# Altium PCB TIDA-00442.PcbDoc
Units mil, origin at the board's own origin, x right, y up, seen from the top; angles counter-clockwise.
Board outline 2800 x 2450 mil, 4 copper layers (Top Layer, GND, POWER, Bottom Layer), stack 90 mil thick; 95 components, 40 nets, 194 pads, 43 vias.
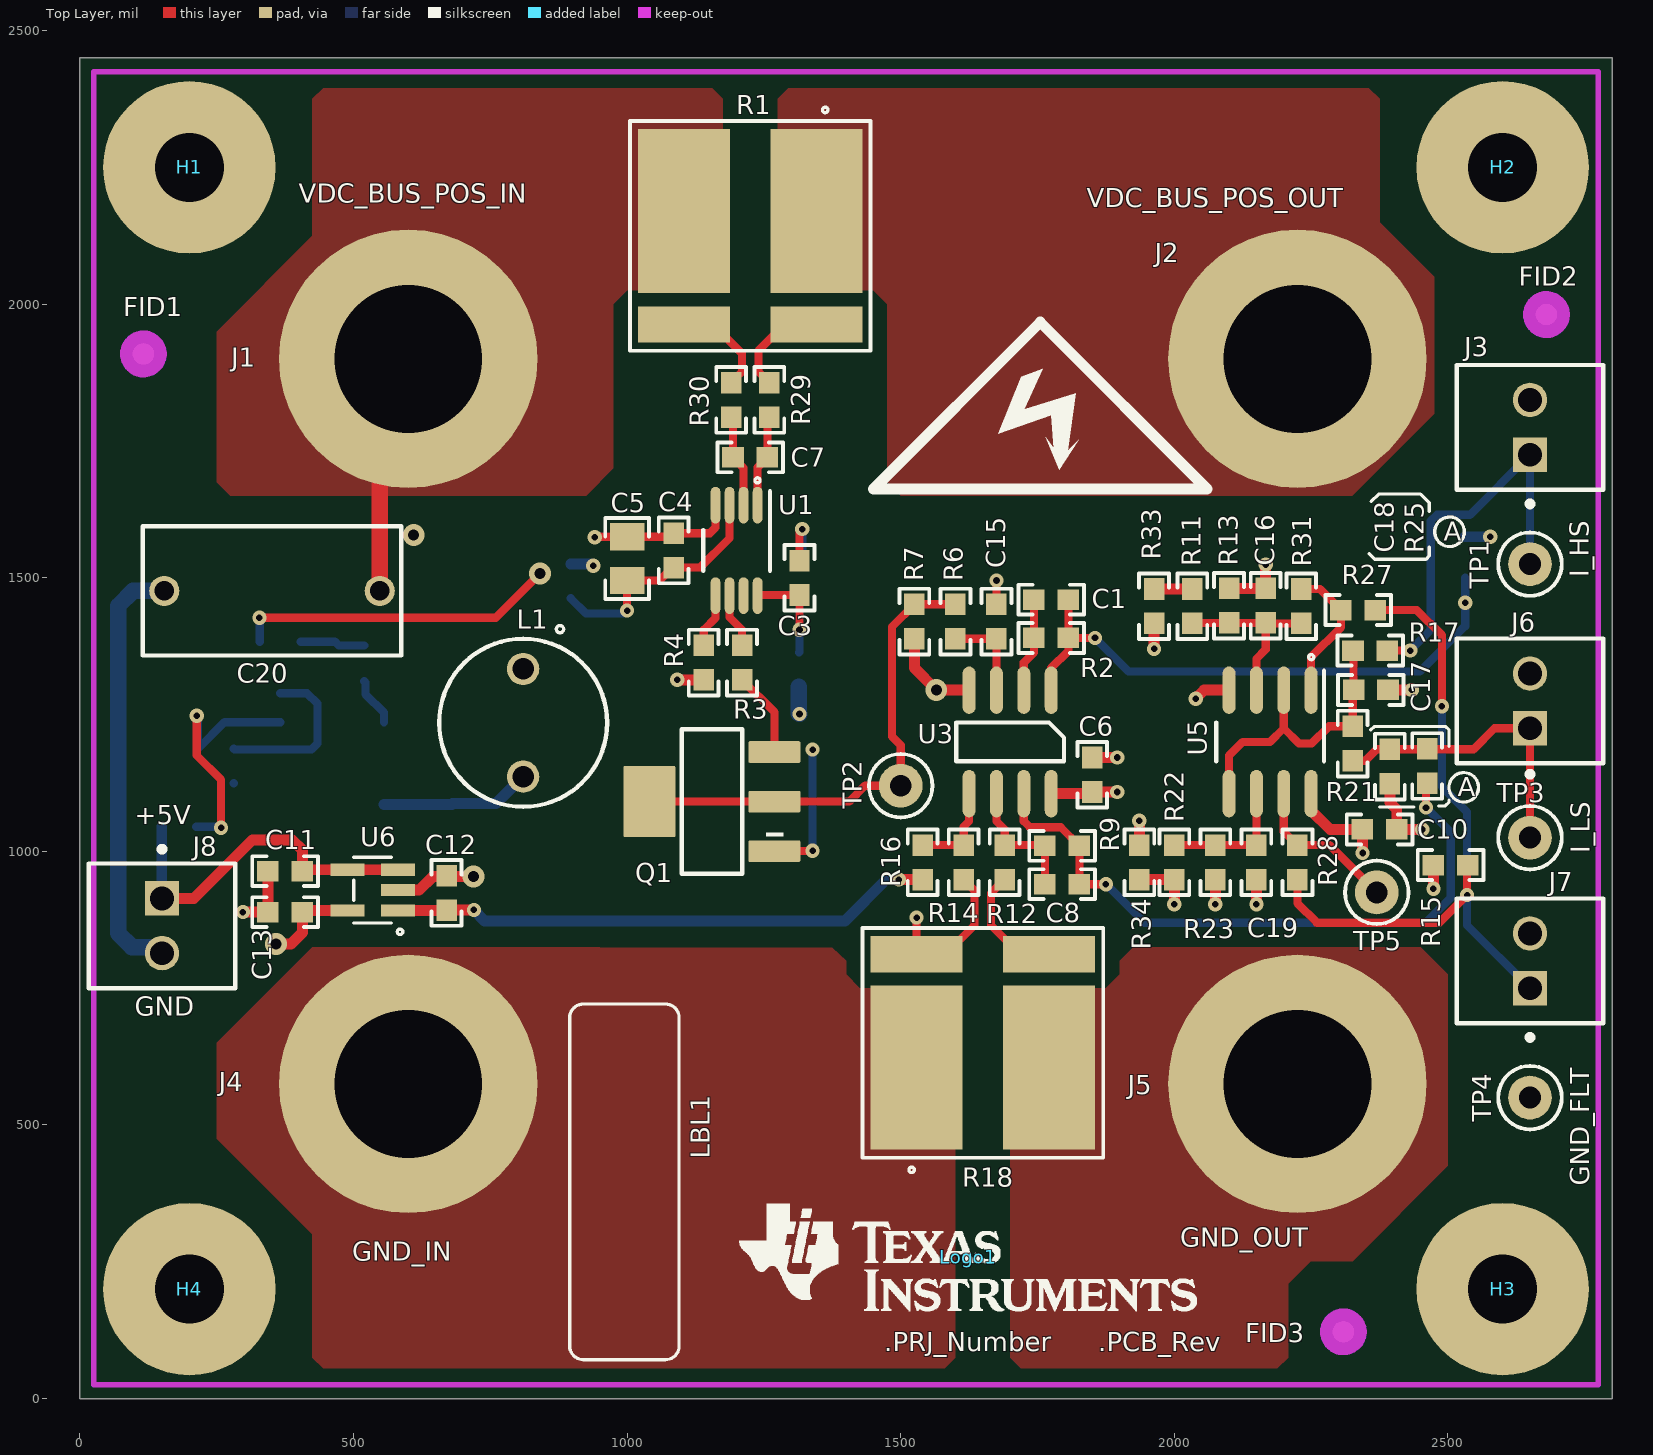
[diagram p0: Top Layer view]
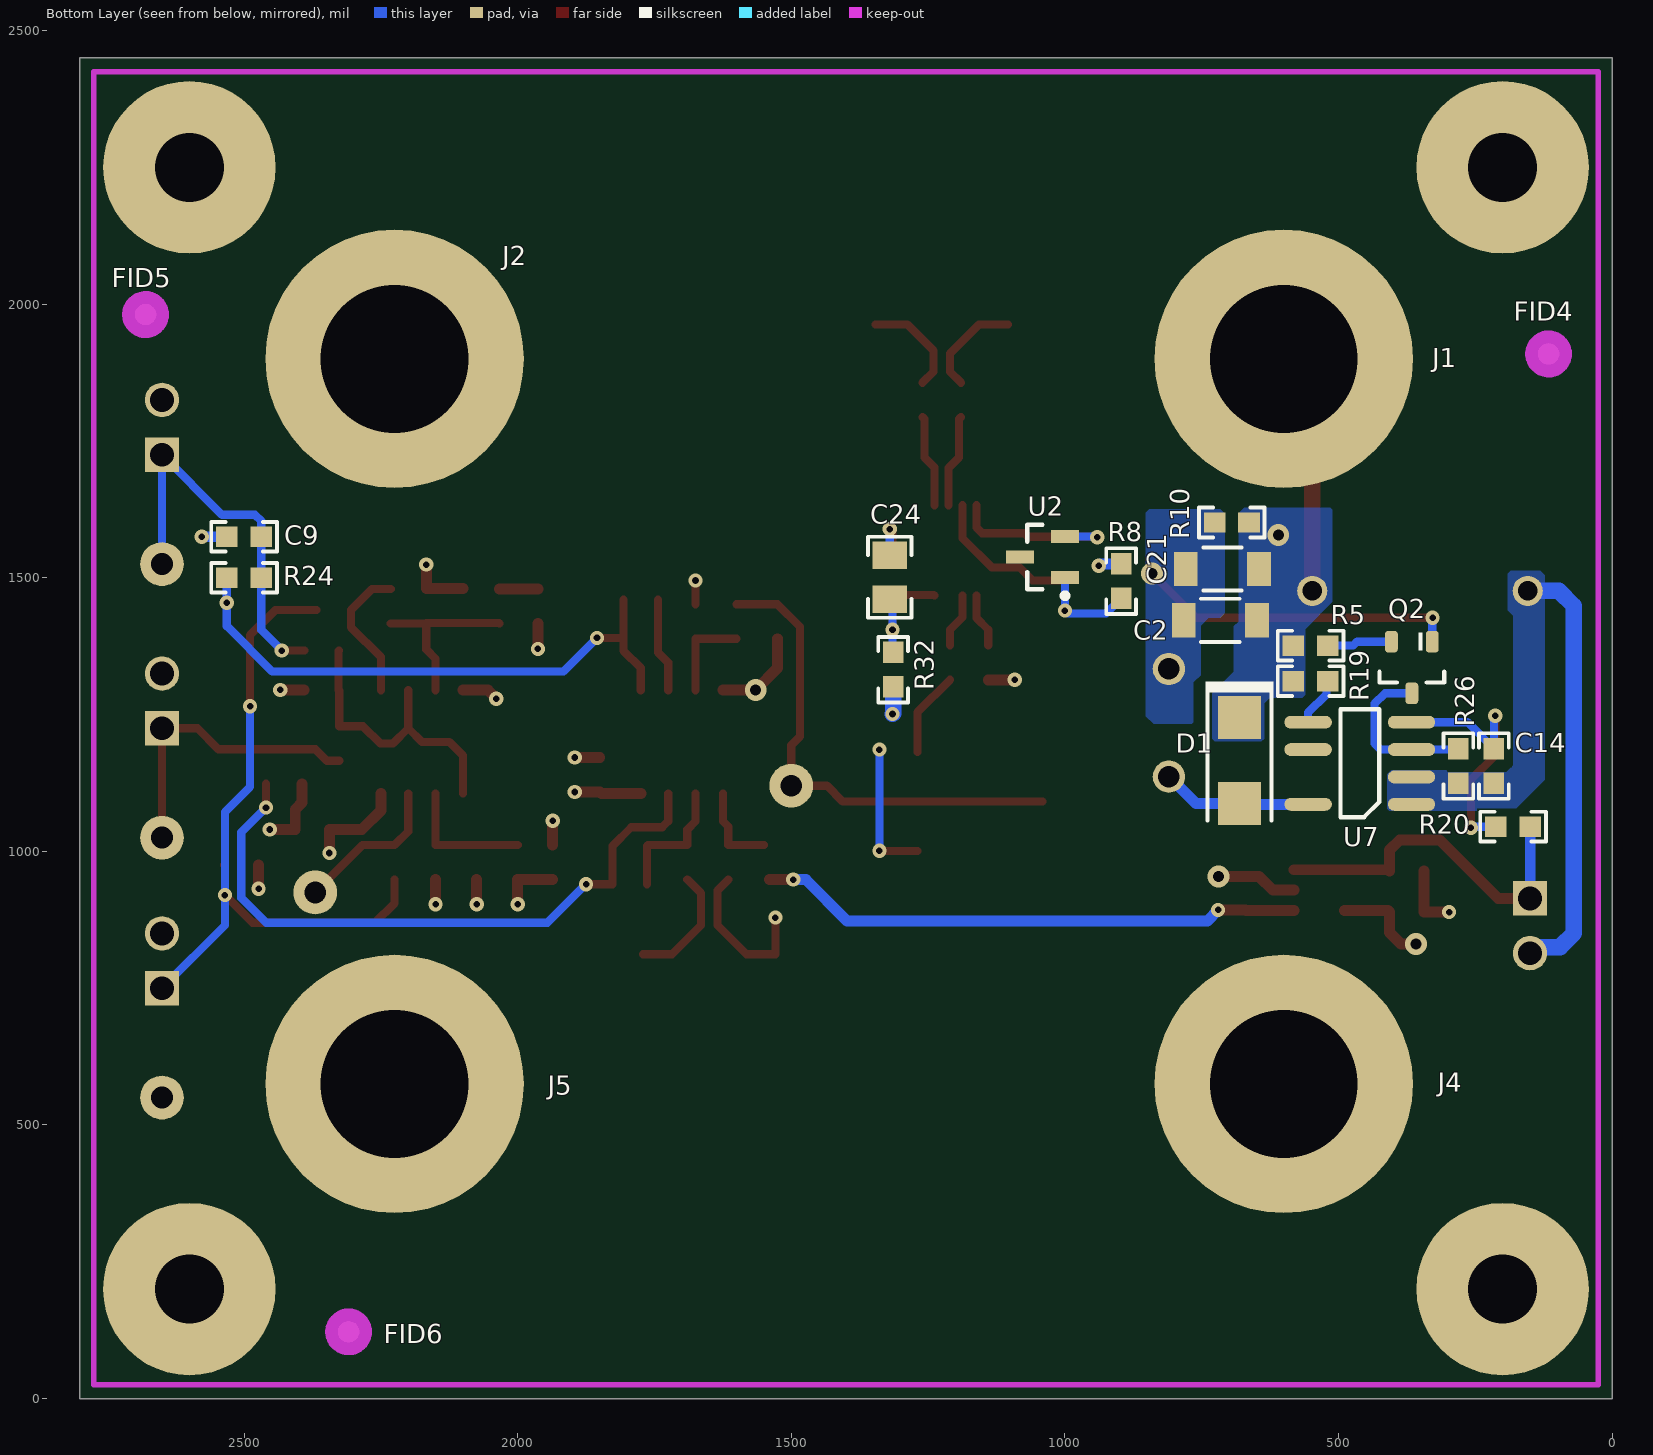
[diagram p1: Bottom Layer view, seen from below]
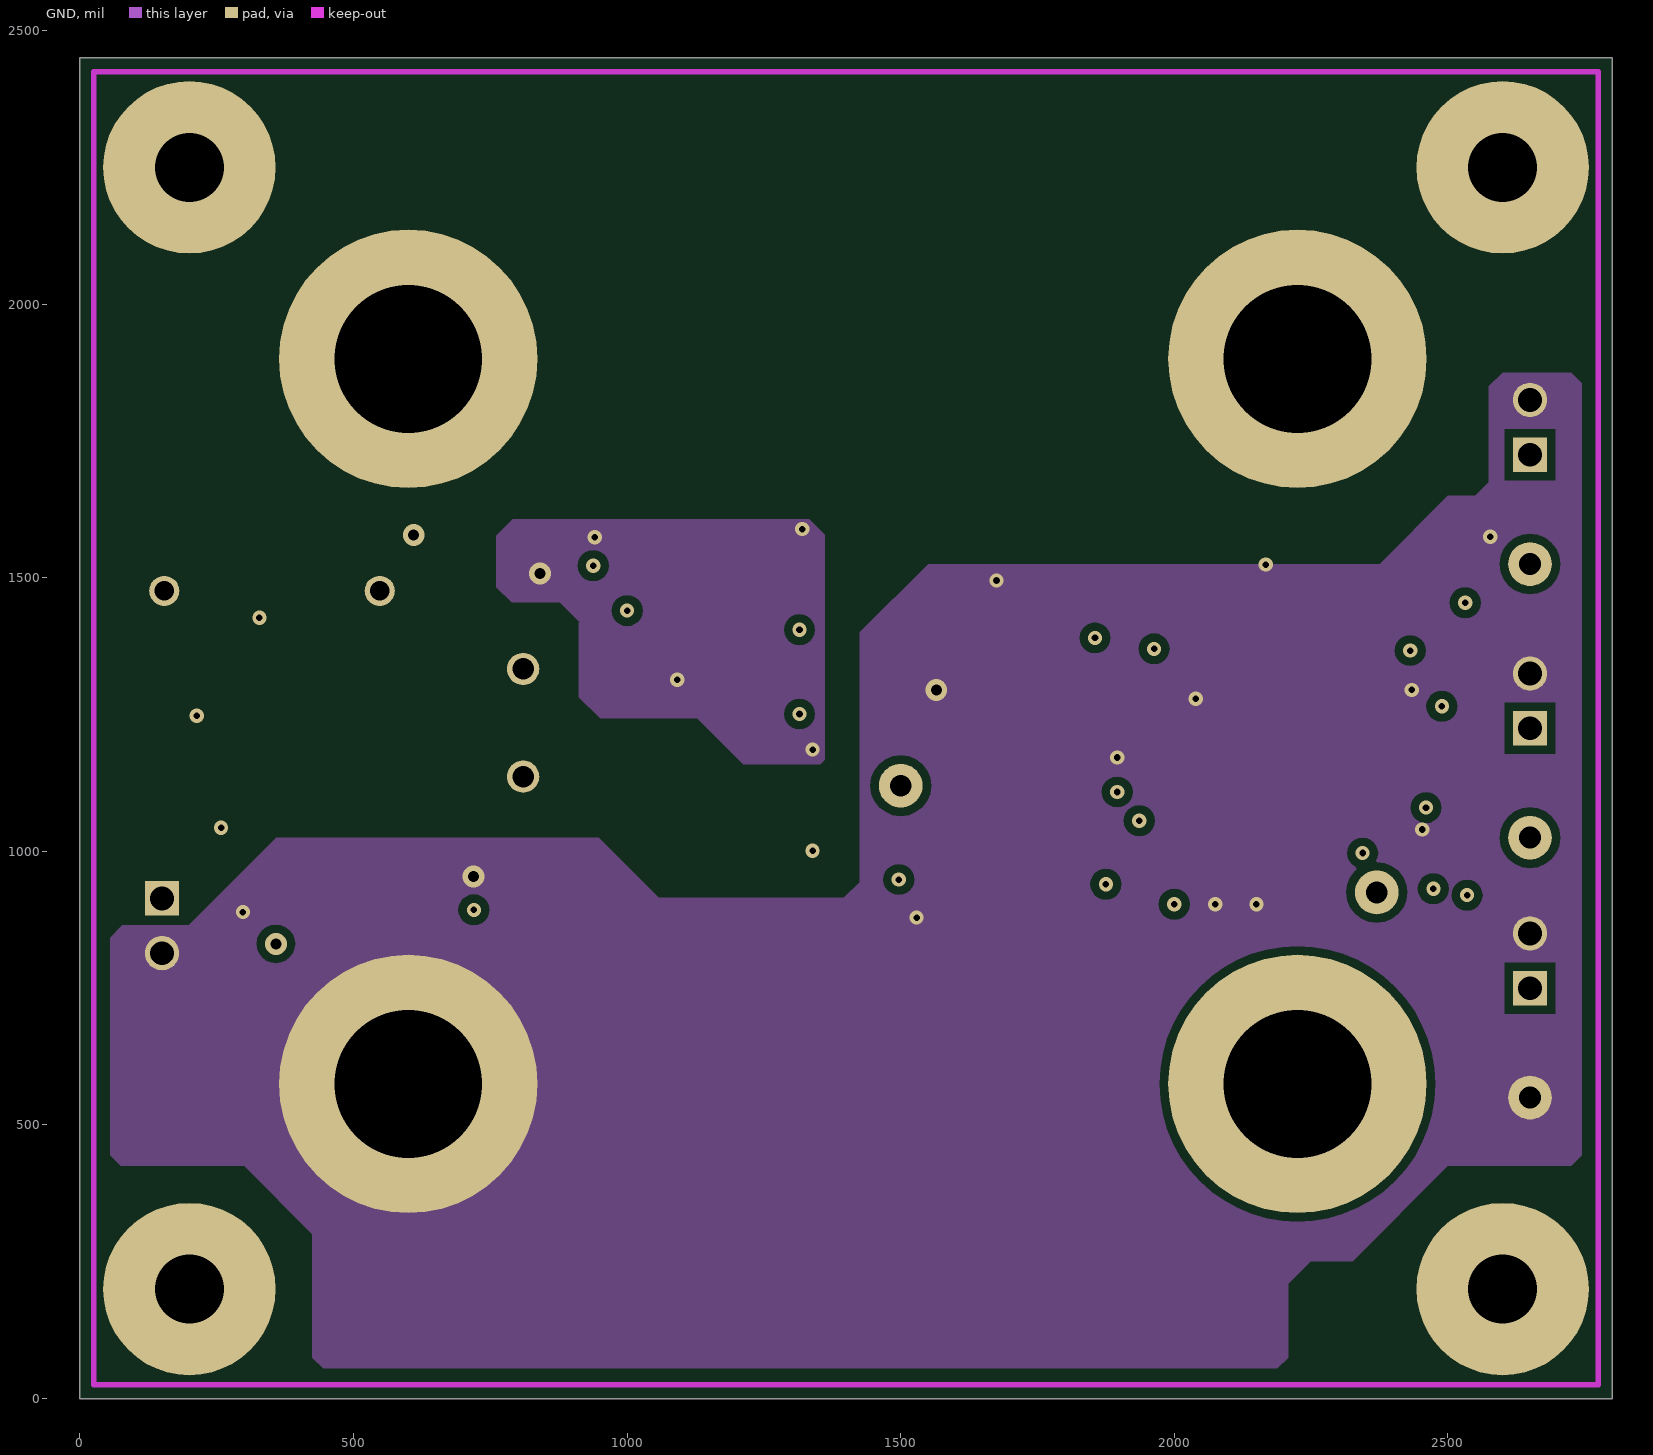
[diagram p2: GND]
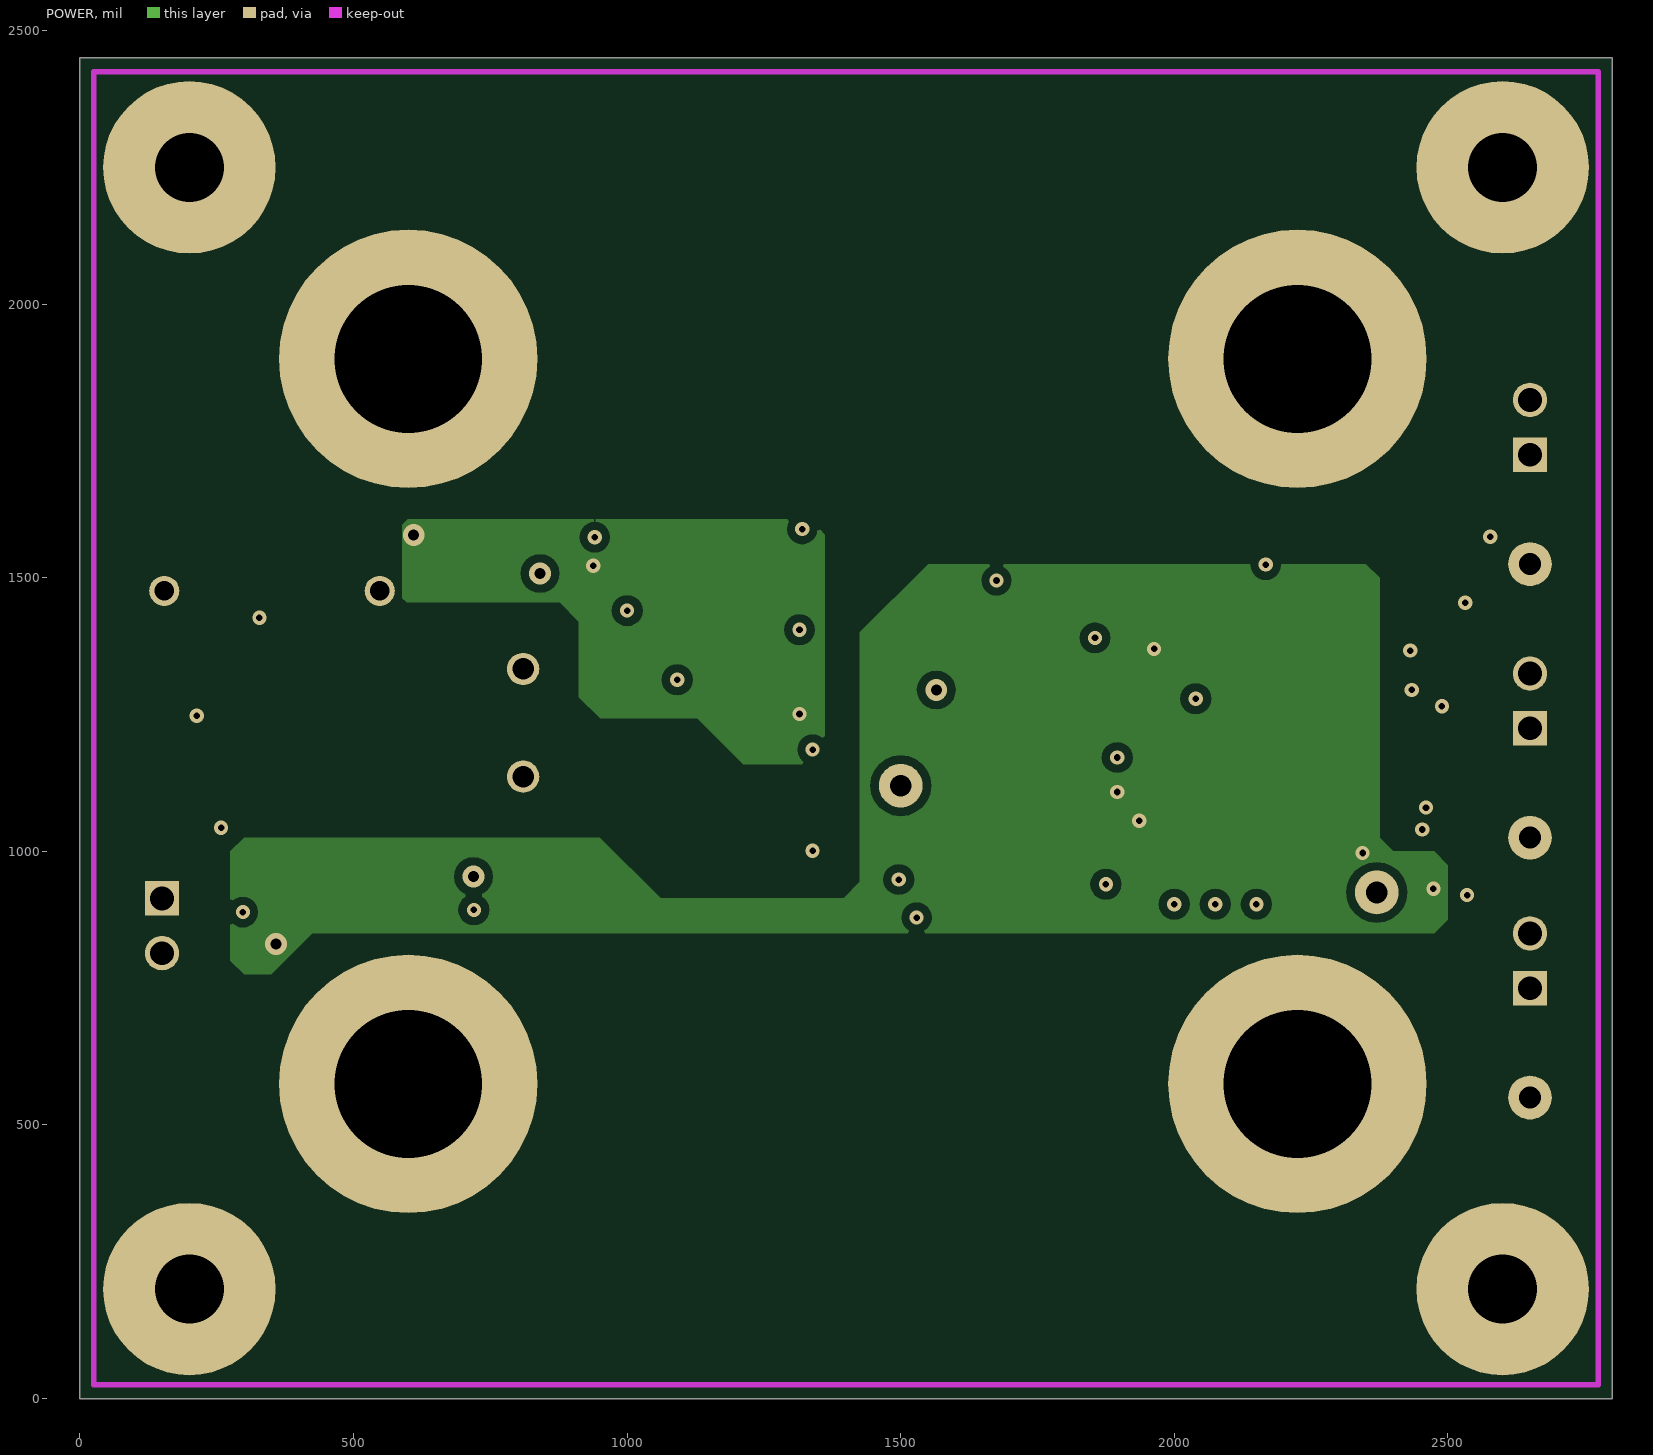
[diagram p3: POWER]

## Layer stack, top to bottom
Top Layer: signal copper 1.4
Dielectric: core 59.2, FR-4, Dk 4.8
GND: signal copper 1.4
Dielectric: prepreg 12.6, FR-4, Dk 4.8
POWER: signal copper 1.4
Dielectric: core 12.6, FR-4, Dk 4.8
Bottom Layer: signal copper 1.4

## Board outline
0,0 0,2450 2800,2450 2800,0

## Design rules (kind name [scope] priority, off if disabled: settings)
AcuteAngle [All] p1: minimum=4.50000000000000E+0001 checktracksonly=FALSE
AssemblyTestPointUsage [All] p1: valid=2
Clearance Poly_Poly [InPolygon vs InPolygon] p1: gap=25
Clearance Clearance_BoardEdge_MountingHoles [OnCopper and InComponentClass('Mounting Holes') vs IsKeepOut] p2: gap=12
Clearance Clearance_BoardEdge_Poly [OnCopper and InPoly vs IsKeepOut] p3: gap=25
Clearance Clearance_BoardEdge [OnCopper and Not InComponentClass('Logo') and not InComponentClass('FiducialMark') and not InRegion(1000,500,4000,800) and Not IsKeepout vs IsKeepOut] p4: gap=25
Clearance Clearance_Poly [InPolygon] p5: gap=15
Clearance [All] p6: gap=7.87
ComponentClearance ComponentClearance_MountingHoles_FiducialMarks [InComponentClass('Mounting Holes') vs InComponentClass('FiducialMark')] p1: gap=50 collisioncheckmode=3 verticalgap=10 showdistances=FALSE
ComponentClearance ComponentClearance_Shunt [InComponentClass('Header') vs InComponentClass('Shunt')] p2: gap=0 collisioncheckmode=3 verticalgap=0 showdistances=FALSE
ComponentClearance ComponentClearance_Logo [InComponentClass('Logo')] p3: gap=50 collisioncheckmode=3 verticalgap=10 showdistances=FALSE
ComponentClearance ComponentClearance_ScrewToNut [(HasFootprint('NY PMS 440 0025 PH')) vs (HasFootprint('Keystone_1902C'))] p4: gap=5 collisioncheckmode=3 verticalgap=10 showdistances=FALSE
ComponentClearance ComponentClearance_MountingHoles [InComponentClass('Mounting Holes')] p5: gap=100 collisioncheckmode=3 verticalgap=0 showdistances=FALSE
ComponentClearance ComponentClearance_SmallPassives [HasFootprint('0201*') or HasFootprint('0402*') or HasFootprint('0508') or HasFootprint('0603*') or HasFootprint('0612') or HasFootprint('0805*') or HasFootprint('0815*') or HasFootprint('0830*') or HasFootprint('1206*') or HasFootprint('1210*') or HasFootprint('1808*') or HasFootprint('1812*') or HasFootprint('1825*') or HasFootprint('2010*') or HasFootprint('2220*') or HasFootprint('2225*') or HasFootprint('2512*') or HasFootprint('2728*') or HasFootprint('3518*') vs HasFootprint('0201*') or HasFootprint('0402*') or HasFootprint('0508') or HasFootprint('0603*') or HasFootprint('0612') or HasFootprint('0805*') or HasFootprint('0815*') or HasFootprint('0830*') or HasFootprint('1206*') or HasFootprint('1210*') or HasFootprint('1808*') or HasFootprint('1812*') or HasFootprint('1825*') or HasFootprint('2010*') or HasFootprint('2220*') or HasFootprint('2225*') or HasFootprint('2512*') or HasFootprint('2728*') or HasFootprint('3518*')] p6: gap=10 collisioncheckmode=3 verticalgap=10 showdistances=FALSE
ComponentClearance ComponentClearance_THtoSMT [IsThruComponent vs IsSMTComponent] p7: gap=40 collisioncheckmode=3 verticalgap=30 showdistances=FALSE
ComponentClearance ComponentClearance_THtoTH [IsThruComponent vs IsThruComponent] p8: gap=65 collisioncheckmode=3 verticalgap=30 showdistances=FALSE
ComponentClearance [All] p9: gap=30 collisioncheckmode=3 verticalgap=10 showdistances=FALSE
DiffPairsRouting [All] p1: maxlimit=100 minlimit=10 mostfreqgap=10 maxuncoupledlength=1000
FabricationTestPointUsage TestPointUsage [All] p1: valid=2 allowmultiple=FALSE
FabricationTestpoint Testpoint [All] p1: side=3 testpointundercomponent=TRUE minsize=40 maxsize=100 preferedsize=60 minholesize=0 maxholesize=40 preferedholesize=32 testpointgrid=1 allowsidetop=TRUE allowsidebottom=TRUE usegrid=TRUE gridtolerance=0.01
FanoutControl Fanout_LCC [IsLCC] p1: bgadir=Out bgaviamode=Centered fanoutstyle=Auto fanoutdirection=Alternating viagrid=1 // Fanout_LCC (Default Rule)
FanoutControl Fanout_BGA [IsBGA] p2: bgadir=Out bgaviamode=Centered fanoutstyle=Auto fanoutdirection=Alternating viagrid=1 // Fanout_BGA (Default Rule)
FanoutControl Fanout_Default [All] p4: bgadir=Out bgaviamode=Centered fanoutstyle=Auto fanoutdirection=Alternating viagrid=1 // Fanout_Default (Default Rule)
FanoutControl Fanout_Small [(CompPinCount < 5)] p5: bgadir=Out bgaviamode=Centered fanoutstyle=Auto fanoutdirection=OutThenIn viagrid=1 // Fanout_Small (Default Rule)
HoleSize [All] p1: absolutevalues=TRUE maxlimit=270 minlimit=8 maxpercent=80.000 minpercent=20.000
MinimumAnnularRing MinimumAnnularRing_ThermalPadVias [IsVia and InAnyComponent] p1: minimumring=5.91
MinimumAnnularRing [All] p2: minimumring=7
MinimumSolderMaskSliver MinimumSolderMaskSliver_Logo [InComponentClass('Logo') vs InComponentClass('Logo')] p1: minsoldermaskwidth=0.7
MinimumSolderMaskSliver [All] p2: minsoldermaskwidth=3.94
PlaneConnect [All] p1: planeconnectstyle=Direct reliefexpansion=10 reliefentries=4 reliefconductorwidth=10 reliefairgap=10
PolygonConnect [All] p1: connectstyle=Direct reliefconductorwidth=10 reliefentries=4 polygonreliefangle="90 Angle"
RoutingVias ThermalPadVias [IsVia and InAnyComponent] p1: holewidth=7.87 width=19.68 viastyle="Through Hole" minholewidth=7.87 minwidth=19.68 maxholewidth=12.99 maxwidth=23.62
RoutingVias [All] p2: holewidth=12 width=26 viastyle="Through Hole" minholewidth=7.87 minwidth=26 maxholewidth=20 maxwidth=40
SilkToSilkClearance SilkToSilkClearance_Pb-FreeLogo [(HasFootprint('Pb-Free_Overlay_Medium') OR HasFootprint('Pb-Free_Overlay_Small')) vs (HasFootprint('Pb-Free_Overlay_Medium') OR HasFootprint('Pb-Free_Overlay_Small'))] p1: silktosilkclearance=0
SilkToSilkClearance [All] p2: silktosilkclearance=5
SilkscreenOverComponentPads "Silk to Solder Mask Opening" [IsPad] p1: minsilkscreentomaskgap=1
SolderMaskExpansion [All] p1: expansion=2.5
Width [All] p1: maxlimit=100 minlimit=6 preferedwidth=10 checkconnectedcopper=TRUE
14 further rules are at their usual default settings.

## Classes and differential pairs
component class Label: LBL1
component class Sh02_Current_sense: C1 C2 C3 C4 C5 C6 C7 C8 C9 C10 C11 C12 C13 C14 C15 C16 C17 C18 C19 C20 C21 C24 D1 J1 J2 J3 J4 J5 J6 J7 J8 L1 Q1 Q2 R1 R2 R3 R4 R5 R6 R7 R8 R9 R10 R11 R12 R13 R14 R15 R16 R17 R18 R19 R20 R21 R22 R23 R24 R25 R26 R27 R28 R29 R30 R31 R32 R33 R34 TP1 TP2 TP3 TP4 TP5 U1 U2 U3 U5 U6 U7
component class AssemblyNote: ZZ1 ZZ2 ZZ3 ZZ4
component class FiducialMark: FID1 FID2 FID3 FID4 FID5 FID6
component class Sh03_TID_Hardware: FID1 FID2 FID3 FID4 FID5 FID6 H1 H2 H3 H4 LBL1 Logo1 ZZ1 ZZ2 ZZ3 ZZ4
component class Logo: Logo1
component class "Mounting Holes": H1 H2 H3 H4

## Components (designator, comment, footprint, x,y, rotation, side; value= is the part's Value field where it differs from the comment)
C1 "GRM1885C1H101JA01D" 0603 1775,1460 r180 top
C2 "CL31A106KBHNNNE" 1206_190 716,1422 r0 bottom
C3 "GRM188R71H104KA93D" 0603 1315,1500 r90 top
C4 "GRM188R71H104KA93D" 0603 1085,1550 r90 top
C5 "GRM21BR71H105KA12L" 0805_HV 1000,1535 r90 top
C6 "GRM188R71H104KA93D" 0603 1850,1140 r270 top
C7 "0603ZC103KAT2A" 0603 1225,1720 r180 top
C8 "GRM1885C1H101JA01D" 0603 1795,940 r180 top
C9 "GRM188R71H104KA93D" 0603 2500,1575 r0 bottom
C10 "GRM188R71H104KA93D" 0603 2375,1040 r180 top
C11 "GRM188R71H104KA93D" 0603 375,964 r180 top
C12 "GRM188R71H104KA93D" 0603 670,924 r90 top
C13 "GRM188R71H104KA93D" 0603 375,889 r180 top
C14 "GRM188R71H104KA93D" 0603 216,1156 r270 bottom
C15 "GRM1885C1H101JA01D" 0603 1675,1420 r90 top
C16 "GRM188R71H821KA01D" 0603 2167,1449 r270 top
C17 "GRM188R71H821KA01D" 0603 2359,1295 r180 top
C18 "GRM188R71H104KA93D" 0603 2394,1155 r270 top
C19 "GRM188R71H821KA01D" 0603 2150,980 r90 top
C20 "ECQ-E6333KF" ECQE_1200x1290x600 351,1476 r180 top
C21 "CL31A106KBHNNNE" 1206_190 712,1516 r0 bottom
C24 "08055C105KAT2A" 0805_HV 1320,1501 r90 bottom
D1 "STTH1R06A" SMA 681,1166 r270 bottom
FID1 "Fiducial" Fiducial10-20 116,1909 r0 top
FID2 "Fiducial" Fiducial10-20 2680,1981 r0 top
FID3 "Fiducial" Fiducial10-20 2309,122 r0 top
FID4 "Fiducial" Fiducial10-20 116,1909 r90 bottom
FID5 "Fiducial" Fiducial10-20 2680,1981 r90 bottom
FID6 "Fiducial" Fiducial10-20 2309,122 r90 bottom
H1 "NY PMS 440 0025 PH" "NY PMS 440 0025 PH" 200,2250 r0 top locked
H2 "NY PMS 440 0025 PH" "NY PMS 440 0025 PH" 2600,2250 r0 top locked
H3 "NY PMS 440 0025 PH" "NY PMS 440 0025 PH" 2600,200 r0 top locked
H4 "NY PMS 440 0025 PH" "NY PMS 440 0025 PH" 200,200 r0 top locked
J1 "3267" Pomona_3267 600,1900 r180 bottom
J2 "3267" Pomona_3267 2225,1900 r180 bottom
J3 "282834-2" TEC_282834-2 2650,1775 r90 top
J4 "3267" Pomona_3267 600,575 r0 bottom
J5 "3267" Pomona_3267 2225,575 r90 bottom
J6 "282834-2" TEC_282834-2 2650,1275 r90 top
J7 "282834-2" TEC_282834-2 2650,800 r90 top
J8 "282834-2" TEC_282834-2 150,864 r270 top
L1 "680 µH" 8095 810,1235 r270 top
LBL1 "Size: 0.65\" x 0.20 \"" Label_650x200 995,396 r90 top
Logo1 "Texas Instruments" TI_Stacked_Overlay_Small 1623.04,258.07 r0 top
Q1 "ZVP0545GTA" SOT-223 1155,1091 r180 top
Q2 "PBHV9050T,215" SOT-23 366,1336 r270 bottom
R1 "WSL36375L000FEA" WSL3637_0.001 1225,2125 r180 top
R2 "RC0603FR-0716KL" 0603 1775,1390 r0 top
R3 "CRCW06034K99FKEA" 0603 1210,1345 r90 top
R4 "RT0603BRD0724K3L" 0603 1140,1345 r90 top
R5 "CRCW06031M47FKEA" 0603 551,1376 r0 bottom
R6 "RC0603JR-070RL" 0603 1600,1420 r270 top
R7 "RG1608P-163-B-T5" 0603 1525,1420 r90 top
R8 "CRCW0603200KFKEA" 0603 897,1494 r90 bottom
R9 "RG1608P-163-B-T5" 0603 1795,1010 r0 top
R10 "CRCW0603402KFKEA" 0603 695,1601 r180 bottom
R11 "RC0603FR-0716KL" 0603 2033,1448 r270 top
R12 "RG1608P-102-B-T5" 0603 1690,980 r270 top
R13 "CRCW060316K2FKEA" 0603 2100,1449 r90 top
R14 "RG1608P-102-B-T5" 0603 1615,980 r90 top
R15 "CRCW060315K0FKEA" 0603 2505,975 r0 top
R16 "RG1608P-163-B-T5" 0603 1540,980 r270 top
R17 "CRCW060316K2FKEA" 0603 2358,1367 r180 top
R18 "WSL36375L000FEA" WSL3637_0.001 1650,650 r0 top
R19 "RC0603JR-070RL" 0603 551,1311 r180 bottom
R20 "RC0603JR-070RL" 0603 181,1045 r180 bottom
R21 "CRCW060316K2FKEA" 0603 2326,1197 r270 top
R22 "CRCW060316K2FKEA" 0603 2000,980 r90 top
R23 "RC0603FR-0716KL" 0603 2075,980 r270 top
R24 "CRCW060338R3FKEA" 0603 2500,1500 r180 bottom
R25 "CRCW060338R3FKEA" 0603 2462,1156 r90 top
R26 "CRCW060351K0JNEA" 0603 281,1156 r90 bottom
R27 "RC0603JR-070RL" 0603 2336,1441 r0 top
R28 "RC0603JR-070RL" 0603 2225,980 r270 top
R29 "CRCW060322R0JNEA" 0603 1260,1825 r270 top
R30 "CRCW060322R0JNEA" 0603 1190,1825 r270 top
R31 "CRCW06035M11FKEA" 0603 2232,1448 r90 top
R32 "RG1608P-103-B-T5" 0603 1314,1332 r270 bottom
R33 "RC0603JR-070RL" 0603 1963,1448 r90 top
R34 "RC0603JR-070RL" 0603 1936,980 r270 top
TP1 "5000" Keystone5000 2650,1525 r90 top
TP2 "5000" Keystone5000 1500,1120 r90 top
TP3 "5000" Keystone5000 2650,1025 r90 top
TP4 "5001" Keystone5001 2650,550 r270 top
TP5 "5000" Keystone5000 2370,925 r0 top
U1 "INA170EA/2K5" DGK0008A_N 1200,1550 r270 top
U2 "LM4040DIM3X-2.5" MF03A_N 1041,1538 r0 bottom
U3 "OPA2376AID" D0008A_N 1700,1200 r270 top
U5 "TLC372CDR" D0008A_N 2175,1200 r270 top
U6 "REF2033AIDDCR" DDC0005A_N 535,929 r180 top
U7 "UCC28880DR" D0007A_N 461,1161 r0 bottom
ZZ1 "This Assembly Note is for PCB labels only" AssemblyNoteLabel 181,3474 r0 top
ZZ2 "These assemblies are ESD sensitive, ESD precautions shall be observed." AssemblyNote 181,3379 r0 top
ZZ3 "These assemblies must be clean and free from flux and all contaminants. Use of no clean flux is not acceptable." AssemblyNote 181,3289.56 r0 top
ZZ4 "These assemblies must comply with workmanship standards IPC-A-610 Class 2, unless otherwise specified." AssemblyNote 181,3201 r0 top

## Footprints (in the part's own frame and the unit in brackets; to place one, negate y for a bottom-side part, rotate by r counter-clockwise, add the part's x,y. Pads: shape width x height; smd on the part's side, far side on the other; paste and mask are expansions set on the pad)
0603 [mm] "0603 from SM-752 data"
  rect 1x0.95 smd: 1(-0.8,0) 2(0.8,0)
  silkscreen extent -1.52,-0.69 1.52,0.69, body extent -0.87,-0.47 0.87,0.47, height 0.85
0805_HV [mil] "0805 with 30mil clearance between pads"
  rect 50x63 smd: 1(-40,0) 2(40,0)
  silkscreen extent -74,-40 74,40, body extent -43,-29 43,29, height 43
1206_190 [mm] "1206_190"
  rect 1.1x1.6 smd: 1(-1.7,0) 2(1.7,0)
  silkscreen extent -0.9,-1 0.9,1, body extent -1.75,-0.95 1.75,0.95, height 1.9
8095 [mm] "THT, 2-PIN, Body (7.8 X7.8 mm),pitch 5mm"
  round 1.5 hole 1 paste+0: 1(-2.5,0) 2(2.5,0)
  silkscreen extent -3.9,-3.9 3.9,3.9, body extent -5.52,-5.52 5.52,5.52, height 9.5
AssemblyNote [mil] "Assembly Note"
AssemblyNoteLabel [mil] "Assembly Note for PCB Labels"
D0007A_N [mm] "SOIC, 7-Leads, Body 4.9x3.9mm, Pitch 1.27mm, IPC Medium Density"
  oval 2.2x0.6 smd: 1(-2.4,1.905) 2(-2.4,0.635) 3(-2.4,-0.635) 4(-2.4,-1.905) 5(2.4,-1.905) 6(2.4,-0.635) 8(2.4,1.905)
  silkscreen extent -0.9,-2.5 0.9,2.5, body extent -3,-2.5 3,2.5, height 1.54
D0008A_N [mm] "SOIC, 8-Leads, Body 4.9x3.9mm, Pitch 1.27mm, IPC Medium Density"
  oval 2.2x0.6 smd: 1(-2.4,1.905) 2(-2.4,0.635) 3(-2.4,-0.635) 4(-2.4,-1.905) 5(2.4,-1.905) 6(2.4,-0.635) 7(2.4,0.635) 8(2.4,1.905)
  silkscreen extent -0.9,-2.5 0.9,2.5, body extent -3,-2.45 3,2.45, height 1.63
DDC0005A_N [mil]
  rect 62x22 smd: 1(-46,37.4) 2(-46,0) 3(-46,-37.4) 4(46,-37.4) 5(46,37.4)
  silkscreen extent -55,-60 35,81, body extent -60,-60 60,60, height 43
DGK0008A_N [mm] "TSOP, 8-Leads, Body 3x3mm, Pitch 0.65mm, IPC Medium Density"
  oval 1.7x0.45 smd mask+0.05: 1(-2.1,0.975) 2(-2.1,0.325) 3(-2.1,-0.325) 4(-2.1,-0.975) 5(2.1,-0.975) 6(2.1,-0.325) 7(2.1,0.325) 8(2.1,0.975)
  silkscreen extent -2.75,-1.55 0.95,1.55, body extent -2.45,-1.5 2.45,1.5, height 0.94
ECQE_1200x1290x600 [mm] "TH, 2-Leads, Body 12x6mm, Pin Spacing 10mm"
  round 1.4 hole 0.9: 1(-5,0) 2(5,0)
  silkscreen extent -6,-3 6,3, body extent -6,-3 6,3, height 12.9
Fiducial10-20 [mm]
  round 1 smd mask+0.5: 1(0,0)
  Top Layer keep-out circle w1.178: c0,0 r0.5
Keystone5000 [mil] "For Keystone 500x miniature loop terminals"
  round 80 hole 40: 1(0,0)
  silkscreen extent -58,-58 58,58, body extent -49,-49 49,49, height 182
Keystone5001 [mil] "For Keystone 500x miniature loop terminals"
  round 80 hole 40: 1(0,0)
  silkscreen extent -58,-58 58,58, body extent -49,-49 49,49, height 182
Label_650x200 [mil] "Thermal Transfer Label"
  round 1 on Mech13: 0(0,0)
  silkscreen extent -325,-100 325,100, body extent -326,-101 326,101, height 1
MF03A_N [mm] "SOT23, 3-Leads, Body 2.9x1.3mm, Pitch 0.95mm, Lead Span 2.4mm, IPC Medium Density"
  rect 1.3x0.6 smd: 1(-1.05,0.95) 2(-1.05,-0.95) 3(1.05,0)
  silkscreen extent -1.17,-1.5 0.7,1.92, body extent -0.7,-1.5 0.7,1.5, height 1.12
"NY PMS 440 0025 PH" [mm] "4-40 nylon screw and mounting hole"
  round 8 hole 3.2: 1(0,0)
  body extent -3.3,-3.3 3.3,3.3, height 2.69
Pomona_3267 [mm] "Standard Uninsulated Banana Jack"
  round 12 hole 6.858: 1(0,0)
  body extent -4.13,-4.82 4.26,4.85, height 2.79
SMA [mm] "Molded Diode, 2-Leads, Body 4.3x2.6mm, IPC Medium Density, based on OnSemi component dimensions and land pattern"
  rect 2x2 smd: 1(-2,0) 2(2,0)
  silkscreen extent -3.66,-1.57 2.79,1.57, body extent -2.6,-1.3 2.6,1.3, height 2.42
SOT-23 [mm] "SOT23, 3-Leads, Body 2.9x1.3mm, Pitch 0.95mm, Lead Span 2.5mm, IPC Medium Density"
  rrect50% 1x0.6 smd: 1(-1.2,0.95) 2(-1.2,-0.95) 3(1.2,0)
  silkscreen extent -1.63,-1.5 0.7,1.5, body extent -1.16,-1.45 1.21,1.45, height 1
SOT-223 [mm] "SOT223/SC73, 4-Leads, Body 6.5x3.5mm, Pitch 2.3mm, Lead Span 7mm, IPC Medium Density"
  rrect10% 2.4x1 smd: 1(-2.9,2.3) 2(-2.9,0) 3(-2.9,-2.3)
  rrect4% 2.4x3.3 smd: 4(2.9,0)
  silkscreen extent -3.33,-3.35 1.4,3.35, body extent -3.5,-3.25 3.5,3.25, height 1.62
TEC_282834-2 [mm] "TEC"
  rect 1.6x1.6 hole 1.1: 1(-1.27,0)
  round 1.6 hole 1.1: 2(1.27,0)
  silkscreen extent -3.66,-3.4 2.9,3.4, body extent -2.77,-3.25 2.77,3.25, height 10.01
TI_Stacked_Overlay_Small [mil]
  silkscreen extent -418,-98 418,98
WSL3637_0.001 [mil] "Vishay WSL3637 recommended land pattern for 0.001 to 0.0019 Ohm"
  rect 168x300 smd: 1(-121,-45) 2(121,-45)
  rect 168x66 smd: 3(-121,162) 4(121,162)
  silkscreen extent -220,-210 220,210, body extent -185,-190 185,190, height 35

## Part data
C1 C8 C15: "CAP, CERM, 100 pF, 50 V, +/- 5%, C0G/NP0, 0603"
C2 C21: "CAP, CERM, 10 µF, 50 V, +/- 10%, X5R, 1206_190"
C3 C4 C6 C9 C10 C11 C12 C13 C14 C18: "CAP, CERM, 0.1 µF, 50 V, +/- 10%, X7R, 0603"
C5 C24: "CAP, CERM, 1 µF, 50 V, +/- 10%, X7R, 0805"
C7: "CAP, CERM, 0.01 µF, 10 V, +/- 10%, X7R, 0603"
C16 C17 C19: "CAP, CERM, 820 pF, 50 V, +/- 10%, X7R, 0603"
C20: "CAP, Film, 0.033 µF, 630 V, +/- 10%, TH"
D1: "Diode, Ultrafast, 600 V, 1 A, SMA"
FID1 FID2 FID3 FID4 FID5 FID6: "Fiducial mark.  There is nothing to buy or mount."
H1 H2 H3 H4: "Machine Screw, Round, #4-40 x 1/4, Nylon, Philips panhead"
J1 J2 J4 J5: "Standard Banana Jack, Uninsulated"
J3 J6 J7 J8: "Terminal Block, 2x1, 2.54mm, TH"
L1: library part "WE-TI HV 8095, 768772681", "SMD-Radial Leaded Wire Wound  Inductor WE-TI HV, L=680 µH"
LBL1: library part THT-14-423-10, "Thermal Transfer Printable Labels, 0.650\" W x 0.200\" H - 10,000 per roll"
Logo1: library part TI_Logo, "Texas Instrument Corporate Signature"
Q1: library part ZXMP6A17GTA, "MOSFET, P-CH, -450 V, 75 mA, SOT-223"
Q2: library part "PBHV9050T,215, NXP Semiconductor", "Transistor, PNP, 500 V, 0.15 A, SOT-23"
R1 R18: library part WSL36371L000FEA, "RES, 0.005, 1%, 3 W, WSL3637"
R2 R11 R23: "RES, 16.0 k, 1%, 0.1 W, 0603"
R3: "RES, 4.99 k, 1%, 0.1 W, 0603"
R4: "RES, 24.3 k, 0.1%, 0.1 W, 0603"
R5: "RES, 1.47 M, 1%, 0.1 W, 0603"
R6 R19 R20 R27 R28 R33 R34: "RES, 0, 5%, 0.1 W, 0603"
R7 R9 R16: "RES, 16.0 k, 0.1%, 0.1 W, 0603"
R8: "RES, 200 k, 1%, 0.1 W, 0603"
R10: "RES, 402 k, 1%, 0.1 W, 0603"
R12 R14: "RES, 1.00 k, 0.1%, 0.1 W, 0603"
R13 R17 R21 R22: "RES, 16.2 k, 1%, 0.1 W, 0603"
R15: "RES, 15.0 k, 1%, 0.1 W, 0603"
R24 R25: "RES, 38.3, 1%, 0.1 W, 0603"
R26: "RES, 51 k, 5%, 0.1 W, 0603"
R29 R30: "RES, 22, 5%, 0.1 W, 0603"
R31: "RES, 5.11 M, 1%, 0.1 W, 0603"
R32: "RES, 10.0 k, 0.1%, 0.1 W, 0603"
TP1 TP2 TP3 TP5: "Test Point, Miniature, Red, TH"
TP4: "Test Point, Miniature, Black, TH"
U1: "High-Side, Bidirectional Current Shunt Monitor, DGK0008A"
U2: "Precision Micropower Shunt Voltage Reference, 3-pin SOT-23"
U3: "Precision, Low Noise, Low Quiescent Current Operational Amplifier, 2 to 5.5 V, -40 to 125 degC, 8-pin SOIC (D0008A), Green (RoHS & no Sb/Br)"
U5: "LinCMOS Dual Differential Comparators, D0008A"
U6: "Low-Drift, Low-Power, Dual-Output, VREF and VREF / 2 Voltage References, DDC0005A"
U7: "700-V Lowest Quiescent Current Off-Line Switcher, D0007A"
ZZ1: library part AssemblyNoteLabel
ZZ2 ZZ3 ZZ4: library part AssemblyNote

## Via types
v1: diameter 26, hole 12, Top Layer to Bottom Layer, tented both sides, 38 vias
v2: diameter 40, hole 20, Top Layer to Bottom Layer, tented both sides, 5 vias

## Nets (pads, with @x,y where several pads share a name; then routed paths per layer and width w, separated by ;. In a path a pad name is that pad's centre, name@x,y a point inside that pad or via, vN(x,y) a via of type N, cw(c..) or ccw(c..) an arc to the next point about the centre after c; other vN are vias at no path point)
DC_BUS_POS: C2.1 C20.1 C21.1 D1.1 J1.1 R1.2 R5.2 R8.2 R10.2 R19.1 R32.2 | length 546
  Top Layer w30: C20.1@547.85,1468 C20.1 547.85,1847.85 J1.1
  Bottom Layer w20: R8.2 934.5,1525.5 v1(938,1522)
  Bottom Layer w30: R32.2 1314,1252 v1(1315,1251)
  other v2: 610,1578
FB: Q2.3 R26.2 U7.3 | length 306.9
  Bottom Layer w15: R26.2 282.5,1186 U7.3 423,1186 434,1197 434,1270 415.24,1288.76 Q2.3
FLOAT_REF: C2.2 C3.2 C4.2 C5.2 C21.2 C24.2 L1.1 Q1.1 Q2.1 R4.1 R10.1 U1.4 U2.2 | length 1330.5
  Top Layer w10: C4.2@1068.5,1575 C4.2@1075,1581.5 ; v1@1338.45,1000.45 v1(1339,1001)
  Top Layer w15: v1(328,1427) 760,1427 v2(841,1508) ; v1(941,1574) 942,1575 C5.2 C4.2@1068.5,1575 ; C4.2@1075,1581.5 1151.5,1581.5 1161.61,1591.61 U1.4 ; Q1.1 v1@1338.45,1000.45 ; C3.2 1315,1584 v1(1320,1589)
  Top Layer w20: v1(1091.5,1313.5) R4.1
  Bottom Layer w15: v1(328,1427) v1@328.6,1427.6 ; Q2.1 v1@328.6,1427 ; v1(941,1574) 942.4,1575.4 U2.2 ; C24.2 v1(1320,1589) ; v1(1339,1001) v1(1339,1186)
GND: C6.1 C9.2 C10.1 C11.2 C12.2 C13.2 C14.2 C15.2 C16.1 C17.1 C18.2 C19.1 C20.2 J3.2 J4.1 J6.2 J7.2 J8.2 R7.1 R13.2 R14.1 R18.1 R18.3 R23.2 R26.1 TP4.1 U3.4 U5.4 U6.2 U7.1 U7.2 | length 2102.1
  Top Layer w10: v1@1673.5,1495 v1@1673.5,1501.5
  Top Layer w15: v1(1529,879) R18.3 1582,812 1635,865 1635,928.5 R14.1 ; v1@1673.5,1495 1675,1493.5 C15.2
  Top Layer w20: v1(297.83,889) C13.2 C11.2 ; U6.2 620,929 645,954 v2(719,954) ; R7.1 1525,1335 v2(1565,1295) 1565.51,1294.49 U3.4 ; C6.1 v1(1895.67,1171.5) ; v1(2039,1279) 2054.49,1294.49 U5.4 ; v1(2075,903.5) R23.2 ; R13.2 C16.1 v1(2167,1524) ; v1(2150,903.5) C19.1 ; C17.1 v1(2434,1295) ; C18.2 2394,1089 2406.5,1076.5 C10.1 v1(2452.99,1040) v1@2455,1042.01
  Bottom Layer w20: C9.2 v1(2577.17,1575)
  Bottom Layer w30: J8.2@150,825 95,825 70,850 70,1449 97,1476 C20.2
  other v1: 1675,1495
GND_FAULT: J7.1 R15.2 R27.2 R28.2 | length 1296.9
  Top Layer w15: R28.2 2225,905 2260.37,869.63 2484.63,869.63 v1(2535,920) 2535,973.5 R15.2 ; R27.2 2443,1441 2489,1395 v1(2489,1265)
  Bottom Layer w15: v1(2489,1265) 2489,1118 2535,1072 v1(2535,920) 2535,865 J7.1
I_HS: C9.1 J3.1 R17.1 R24.2 TP1.1 | length 725.4
  Top Layer w15: R17.1 v1(2431,1367)
  Bottom Layer w15: v1(2431,1367) 2468.5,1404.5 R24.2 C9.1 2468.5,1603.5 2480,1615 2540,1615 J3.1 TP1.1
I_LS: C18.1 J6.1 R21.2 R25.2 TP3.1 | length 548.6
  Top Layer w15: R21.2 2348.5,1165.5 2369.5,1186.5 C18.1 2460,1186.5 2546.5,1186.5 2585,1225 J6.1 TP3.1
NetC1_1: C1.1 R2.2 R24.1 U3.1 | length 1051.8
  Top Layer w15: U3.1 1775,1335 1806.5,1366.5 R2.2 ; C1.1 R2.2 ; v1(1855,1390) R2.2
  Bottom Layer w15: v1(1855,1390) 1916.37,1328.63 2448.63,1328.63 2531.5,1411.5 v1(2531.5,1454.33) R24.1
NetC1_2: C1.2 R2.1 U3.2 | length 173.2
  Top Layer w15: U3.2 1725,1345 1743.5,1363.5 R2.1 C1.2
NetC3_1: C3.1 C24.1 R32.1 U1.8 | length 240.6
  Top Layer w15: U1.8 1239.57,1468.5 C3.1 v1(1315,1405)
  Bottom Layer w15: R32.1 1315,1364.5 1315,1417 1315,1456 C24.1
NetC7_1: C7.1 R29.2 U1.1 | length 169.8
  Top Layer w15: U1.1 1238.39,1701.89 C7.1 1256.5,1790 R29.2
NetC7_2: C7.2 R30.2 U1.2 | length 170.3
  Top Layer w15: R30.2 1193.5,1790 C7.2 1212.8,1700.71 U1.2
NetC8_1: C8.1 R9.2 R25.1 U3.7 | length 1194.2
  Top Layer w15: U3.7 1725,1055 1735.93,1044.07 1792.42,1044.07 R9.2 C8.1 v1(1875,940) ; v1(2460,1080) R25.1@2460,1123.5
  Bottom Layer w15: v1(1875,940) 1945.37,869.63 2459.63,869.63 2505,915 2505,1035 v1(2460,1080)
NetC8_2: C8.2 R9.1 R12.1 U3.6 | length 244.4
  Top Layer w15: U3.6 1675,1055 1690,1040 R12.1 1762.01,1011.5 R9.1 C8.2
NetC14_1: C14.1 R20.1 U7.4 | length 504
  Top Layer w15: v1(213.5,1248) 213.5,1175.5 258,1131 v1(258,1043)
  Bottom Layer w15: R20.1 256,1045 v1(258,1043) ; v1(213.5,1248) 212,1248 216,1244 C14.1 264.5,1236 U7.4
NetC15_1: C15.1 R6.2 U3.3 | length 169
  Top Layer w15: R6.2 C15.1 U3.3
NetC16_2: C16.2 R11.2 R13.1 R31.1 U5.3 | length 329.9
  Top Layer w15: R11.2 2034,1417.5 R13.1 C16.2 ; U5.3 2150,1352 2167,1369 C16.2 ; R31.1 2168,1416.5 C16.2
NetC17_2: C17.2 R17.2 R21.1 U5.2 U5.5 | length 549.9
  Top Layer w15: U5.5 2100,1175 2125,1200 2175,1200 2200,1225 ; U5.2 2200,1225 ; R17.2 2327.5,1366 C17.2 2326,1293.5 R21.1 2282.5,1228.5 2251,1197 2228,1197 2200,1225
NetC19_2: C19.2 R22.2 R23.1 U5.6 | length 244
  Top Layer w15: R22.2 R23.1 C19.2 U5.6
NetD1_2: D1.2 L1.2 U7.8 | length 275.5
  Bottom Layer w20: U7.8 679.74,1086 D1.2 760.68,1087.26 L1.2
NetJ2_1: J2.1 R1.1
NetJ5_1: J5.1 R18.2
NetQ1_2: Q1.2 Q1.4 R6.1 R7.2 TP2.1 | length 901.3
  Top Layer w15: Q1.4 Q1.2 1406,1091 1435,1120 TP2.1 1500,1194 1484,1210 1484,1410.5 R7.2 R6.1
NetQ1_3: Q1.3 R3.1 | length 156.5
  Top Layer w15: R3.1 1269.17,1254.33 Q1.3
NetQ2_2: Q2.2 R5.1 | length 119.1
  Bottom Layer w15: Q2.2 465.76,1383.24 473,1376 R5.1
NetR1_3: R1.3 R29.1 | length 192.7
  Top Layer w15: R29.1 1240,1876.5 1240,1915 1288,1963 R1.3
NetR1_4: R1.4 R30.1 | length 189.7
  Top Layer w15: R1.4 1157,1963 1210,1910 1210,1876.5 R30.1
NetR3_2: R3.2 U1.6 | length 100.3
  Top Layer w15: U1.6 1187.2,1427.8 1210,1405 R3.2
NetR4_2: R4.2 U1.5 | length 99.8
  Top Layer w15: R4.2 1140,1405 1161.61,1426.61 U1.5
NetR11_1: R11.1 R33.2 | length 70
  Top Layer w20: R33.2 R11.1
NetR12_2: R12.2 R18.4 | length 221.8
  Top Layer w15: R12.2 1665,923.5 1665,865 1718,812 R18.4
NetR14_2: R14.2 R16.1 U3.5 | length 163.2
  Top Layer w15: R16.1@1550,1011.5 R14.2 1615,1045 1625,1055 U3.5
NetR19_2: R19.2 U7.5 | length 89.9
  Bottom Layer w15: R19.2 522,1308.5 522,1287 555.49,1253.51 U7.5
NetR22_1: R22.1 R34.2 | length 109
  Top Layer w20: R34.2 R22.1 v1(2000,903.5)
NetR27_1: R27.1 R31.2 U5.1 | length 257.5
  Top Layer w15: R31.2 2266.01,1479.5 R27.1 2304.5,1409.5 2250,1355 U5.1
NetR28_1: R28.1 TP5.1 U5.7 | length 285.2
  Top Layer w15: U5.7 2200,1036.5 R28.1 2283.5,1011.5 TP5.1
P3P3V: C6.2 C10.2 C13.1 R15.1 R33.1 R34.1 U3.8 U5.8 U6.5 | length 614.1
  Top Layer w20: v2(358,831) 386,831 406.5,851.5 C13.1 409.09,891.6 U6.5 ; U3.8 C6.2@1847.01,1105.51 ; C6.2 v1(1895.67,1108.5) ; R34.1 v1(1936,1056) ; v1(1963,1370) R33.1 ; U5.8 2250,1075 2285,1040 C10.2 2343.5,997.5 v1(2344,997) ; R15.1 v1(2473.5,931.5) v1@2475,930
P5V: C11.1 J8.1 R20.2 U6.3 U6.4 | length 653.7
  Top Layer w20: J8.1 208,914 315,1021 388,1021 406.5,1002.5 C11.1 408.9,966.4 U6.4 U6.3
  Bottom Layer w20: R20.2 149.5,914.5 J8.1
VREF_1P65V: C12.1 R16.2 U6.1 | length 999.2
  Top Layer w20: U6.1 669.09,891.6 C12.1 v1@720.5,892.5 ; v1(1496.5,948.5) R16.2
  Bottom Layer w20: v1@720,892.5 739.5,873 1398,873 1473.5,948.5 v1(1496.5,948.5)
  other v1: 720,893
VREF_2P5V: C4.1 C5.1 R8.1 U1.3 U2.1 | length 512.3
  Top Layer w15: v1(1000,1440) C5.1 1059,1495 1082.5,1518.5 1133.5,1518.5 1187.2,1572.2 U1.3
  Bottom Layer w15: R8.1 925,1434.5 994.5,1434.5 v1(1000,1440) 999.66,1440.34 U2.1
pads on no net: FID1.1 FID2.1 FID3.1 FID4.1 FID5.1 FID6.1 H1.1 H2.1 H3.1 H4.1 LBL1.0 U1.7 U2.3 U7.6

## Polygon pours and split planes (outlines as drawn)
NetJ5_1 on Top Layer "Multi-Layer-No Net" (solid, remove dead copper, pour order 18): 1725,50 1700,75 1700,725 1725,750 1875,750 1900,775 1900,800 1925,825 2450,825 2500,775 2500,425 2326,251 2249,251 2208,210 2208,75 2183,50
DC_BUS_POS on Top Layer "Multi-Layer-No Net" (solid, remove dead copper, pour order 12): 250,1950 425,2125 425,2375 450,2400 1150,2400 1175,2375 1175,2050 1150,2025 1000,2025 975,2000 975,1700 925,1650 275,1650 250,1675
NetJ2_1 on Top Layer "Multi-Layer-No Net" (solid, remove dead copper, pour order 15): 1275,2375 1275,2050 1300,2025 1450,2025 1475,2000 1475,1675 1500,1650 2325,1650 2475,1800 2475,2050 2375,2150 2375,2375 2350,2400 1300,2400
GND on Top Layer "Multi-Layer-No Net" (solid, remove dead copper, pour order 17): 250,650 425,825 950,825 1375,824.2 1400,800 1400,775 1425,750 1575,750 1600,725 1600,75 1575,50 450,50 425,75 425,300 250,475
DC_BUS_POS on POWER "Multi-Layer-No Net" (solid, remove dead copper, pour order 22): 589,1597 589,1463 597,1455 877,1455 912,1420 912,1282 951,1243 1128,1243 1212,1159 1353,1159 1361,1167 1361,1579 1333,1607 599,1607
P3P3V on POWER "Multi-Layer-No Net" (solid, remove dead copper, pour order 20): 950,1025 1061,914 1395.43,914 1425,944.21 1425,1400 1550,1525 2350,1525 2375,1500 2375,1025 2400,1000 2475,1000 2500,975 2500,875 2475,850 425,850 350,775 300,775 275,800 275,1000 300,1025
GND on GND "Multi-Layer-No Net" (solid, remove dead copper, pour order 14): 50,837 77.24,865 199,865 359,1025 948.2,1024.54 1058,915 1396,915 1425,944 1425,1400 1550,1525 2375,1525 2500,1650 2550,1650 2575,1675 2575,1850 2600,1875 2725,1875 2750,1850 2750,450 2725,425 2500,425 2326,251 2249,251 2208,210 2208,75 2188,55 444.74,55.26 425,75 425,300 300,425 75,425 50,450
FLOAT_REF on GND "Multi-Layer-No Net" (solid, remove dead copper, pour order 21): 761,1577 761,1483 789,1455 877,1455 913,1419 912,1418 912,1282 951,1243 1128,1243 1212,1159 1353,1159 1361,1167 1361,1579 1333,1607 791,1607
GND on Bottom Layer "Multi-Layer-No Net" (solid, remove dead copper, pour order 16): 123,1505 123,1131 180,1074 407,1074 411,1078 411,1141 404,1148 303,1148 300,1145 193,1145 181,1157 181,1431 191,1441 191,1507 185,1513 131,1513
DC_BUS_POS on Bottom Layer "Multi-Layer-No Net" (solid, remove dead copper, pour order 13): 515,1628 511,1624 511,1456 561,1406 561,1286 566,1281 626,1281 636,1271 636,1206 641,1201 726,1201 731,1206 731,1288.67 691,1328.67 691,1411 682,1420 682,1618 672,1628
FLOAT_REF on Bottom Layer "Multi-Layer-No Net" (solid, remove dead copper, pour order 19): 768,1233 838,1233 852,1247 852,1619 846,1625 716,1625 708,1617 708,1435 716,1427 737,1427 752,1412 752,1322 765,1309 765,1236

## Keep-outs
Keep-Out Layer:
  lines w10: 25,25 25,2425 2775,2425 2775,25 25,25
  text ".Layer_Name" at 577,-858.49 h60

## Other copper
Top Layer:
  text ".Layer_Name" at 577,-858.49 h60
GND:
  text ".Layer_Name" at 701,-865.49 h60
POWER:
  text ".Layer_Name" at 697,-866 h60
Bottom Layer:
  text ".Layer_Name" at 577,-858.49 h60

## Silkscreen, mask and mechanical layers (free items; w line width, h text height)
Top Overlay:
  circle w6: c2250.3,1355 r4.7
  circle w6: c1238.3,1678 r4.7
  circle w6: c877.29,1406 r6.71
  circle w6: c2529,1117 r27
  circle w6: c2503,1584 r27
  circle w6: c1520,418 r5
  circle w6: c1362,2355 r5
  region: 1678,1763 1720,1867 1760,1882 1726,1808 1820,1837 1805,1732 1825,1752 1790,1697 1765,1757 1780,1737 1775,1797
  lines w6: 2356,1544.01 2366.01,1534 2460,1534 2466,1540 2466,1556 ; 2359,1222 2365,1228 2382,1228 2496,1228 2502,1222 2502,1192 ; 2360.01,1639.47 2373.54,1653 2450,1653 2466,1637 2466,1621 ; 2375,1081 2438,1081 ; 2483,1083 2495,1083 2502,1090 2502,1094
  lines w20: 1450,1662 1470,1662 2060,1662 1755,1967 1450,1662
  text "VDC_BUS_POS_IN" at 400,2185 h35
  text "VDC_BUS_POS_OUT" at 1840,2177 h35
  text "J2" at 1964,2077 h35
  text "J1" at 277,1886 h35
  text "A" at 2492,1568 h35
  text "I_HS" at 2757,1501 h35 r90
  text "A" at 2518,1101 h35
  text "+5V" at 100,1050 h35
  text "I_LS" at 2759,997 h35 r90
  text "GND" at 100,700 h35
  text "J4" at 254,562 h35
  text "J5" at 1915,556 h35
  text "GND_FLT" at 2758,389 h35 r90
  text "GND_OUT" at 2011,277 h35
  text "GND_IN" at 498,252 h35
  text ".PRJ_Number" at 1470,86 h35
  text ".PCB_Rev" at 1861,86 h35
  text ".Layer_Name" at 577,-858.49 h60
Bottom Overlay:
  text ".Layer_Name" at 577,-858.49 h60
Top Paste:
  text ".Layer_Name" at 577,-858.49 h60
Bottom Paste:
  text ".Layer_Name" at 577,-858.49 h60
Top Solder:
  text ".Layer_Name" at 577,-858.49 h60
  text ".Layer_Name" at 577,-858.49 h60
Bottom Solder:
  text ".Layer_Name" at 577,-858.49 h60
M1 Board Outline:
  the board outline again, w10
M2 Board Dimensions:
  rectangle: 125,-400 500,-275
  rectangle: 0,-275 125,-150
  lines w7: 0,-275 1000,-275 ; 125,-400 125,-150 ; 250,-400 250,-150 ; 500,-400 500,-150 ; 750,-400 750,-150 ; 0,-400 0,-150 1000,-150 1000,-400 0,-400
M3 3D STEP Top:
  text ".Layer_Name" at 577,-858.49 h60
M4 3D STEP Bottom:
  text ".Layer_Name" at 577,-858.49 h60
M5 Assembly Top:
  circle w6: c877,1270 r5.39
  circle w6: c612,891.6 r5
  circle w6: c1313,1000 r5
  circle w6: c1344,2172 r5
  circle w6: c1527,607 r5
  lines w10: -292,-930.17 6308,-930.17 ; -292,-726.83 6310,-726.83 ; -292,-523.5 -292,-1133.5 3713,-1133.5 6310,-1133.5 6310,-523.5 -291.5,-523.5 -291.5,-1133.5 1284,-1133.5 ; 2173,-1133.5 2173,-523.5 ; 3440,-726.83 3440,-523.5 ; 4280,-726.83 4280,-523.5 ; 4902,-1140 4902,-937.17
  text "J1" at 573,1879 h35
  text "J2" at 2191.69,1879 h35
  text "J4" at 564,561 h35
  text "J5" at 2198,557 h35
  text "COMPONENTS MARKED 'DNP' SHOULD NOT BE POPULATED." at 1153.5,-318.5 h35
  text "ASSEMBLY VARIANT:" at 1153,-434 h35
  text ".VariantName" at 2189,-434 h35
  text "PCB VIEWED FROM TOP SIDE" at -228.5,-655.67 h35
  text "BOARD #:" at 2248,-655.67 h35
  text ".PRJ_Number" at 2793.5,-655.67 h35
  text "REV:" at 3638,-655.67 h35
  text ".PCB_Rev" at 3929.5,-655.67 h35
  text "SVN REV:" at 4476,-655.67 h35
  text ".VersionControl_RevNumber" at 4982,-655.67 h35
  text "LAYER NAME =" at -209.5,-857.49 h35
  text ".Layer_Name" at 545,-857.49 h35
  text "PLOT NAME =" at -228.5,-1064.34 h35
  text ".plot_File_Name" at 577,-1064.34 h35
  text "GENERATED    :" at 2250,-1064.34 h35
  text ".Print_Date" at 3119.5,-1064.34 h35
  text ".Print_Time" at 3848.5,-1064.34 h35
  text "TEXAS INSTRUMENTS" at 5113,-1064.34 h35
M6 Assembly Bottom:
  circle w6: c319.44,1321 r3.56
  circle w6: c400.88,1060 r4.12
  circle w6: c991,1481 r5
  lines w6: 1030,1480.94 1057.56,1480.94 1057.56,1512.44 ; 1030,1599.06 1057.56,1599.06 1057.56,1567.56
  lines w10: -292.5,-727.33 6309.5,-727.33 ; -290.5,-930.67 6309.5,-930.67 ; 1115.5,-1140.5 1115.5,-937.67 ; 1737.5,-727.33 1737.5,-524 ; 2577.5,-727.33 2577.5,-524 ; 3844.5,-1134 3844.5,-524 ; 4733.5,-1134 6309,-1134 6309,-524 -292.5,-524 -292.5,-1134 2304.5,-1134 6309.5,-1134 6309.5,-524
  text "COMPONENTS MARKED 'DNP' SHOULD NOT BE POPULATED." at 6102,-318 h35
  text ".VariantName" at 5058,-434 h35
  text "ASSEMBLY VARIANT:" at 6097,-434 h35
  text ".VersionControl_RevNumber" at 1035.5,-656.17 h35
  text "SVN REV:" at 1541.5,-656.17 h35
  text ".PCB_Rev" at 2088,-656.17 h35
  text "REV:" at 2379.5,-656.17 h35
  text ".PRJ_Number" at 3224,-656.17 h35
  text "BOARD #:" at 3769.5,-656.17 h35
  text "PCB VIEWED FROM BOTTOM SIDE" at 6246,-656.17 h35
  text "LAYER NAME =" at 6237,-867 h35
  text ".Layer_Name" at 5449,-871 h35
  text "TEXAS INSTRUMENTS" at 904.5,-1064.84 h35
  text ".Print_Time" at 2169,-1064.84 h35
  text ".Print_Date" at 2898,-1064.84 h35
  text "GENERATED    :" at 3767.5,-1064.84 h35
  text ".plot_File_Name" at 5440.5,-1064.84 h35
  text "PLOT NAME =" at 6246,-1064.84 h35
M9 Title Sheet:
  drawing of 57 lines, arcs and shapes, not listed
  text "1" at 739.84,8036.5 h70
  text "2" at 3235.5,8036.5 h70
  text "3" at 5724.84,8036.5 h70
  text "4" at 8231.51,8036.5 h70
  text "5" at 10730.5,8036.5 h70
  text "6" at 13235.5,8036.5 h70
  text "A" at -416.5,6893.5 h70
  text "A" at 14383.5,6893.5 h70
  text "B" at -416.5,4513.5 h70
  text "B" at 14383.5,4513.5 h70
  text "C" at -416.5,2138.5 h70
  text "C" at 14383.5,2138.5 h70
  text "PROJECT TITLE:" at 11343.5,277.5 h45
  text ".PRJ_Title" at 11393.5,144.17 h70
  text "DESIGNED FOR:" at 11343.5,-23.5 h45
  text ".PRJ_Customer" at 11393.5,-163.5 h70
  text "D" at -416.5,-231.5 h70
  text "D" at 14383.5,-231.5 h70
  text "FILE NAME:" at 11343.5,-323.5 h45
  text ".PCB_File_Name_No_Path" at 11393.5,-443.5 h70
  text "Texas Instruments (TI) and/or its licensors do not warrant the accuracy or completeness of this specification" at 6374,-605.34 h45
  text "ENGINEER:" at 11343.5,-613.5 h45
  text "LAYOUT BY:" at 12848.5,-613.5 h45
  text "or any information contained therein. TI and/or its licensors do not warrant that this design will meet" at 6329.01,-718 h45
  text ".PRJ_Engineer" at 11393.5,-768.49 h70
  text ".PCB_Layout" at 12899,-768.49 h70
  text "the specifications, will be suitable for your application or fit for any particular purpose, or will operate in" at 6329.01,-830.67 h45
  text "ALTIUM DESIGNER VERSION:" at 12848.5,-923.5 h45
  text "an implementation. TI and/or its licensors do not warrant that the design is production worthy. You should" at 6329.01,-943.33 h45
  text "completely validate and test your design implementation to confirm the system functionality for your application." at 6374,-1056 h45
  text ".print_Scale" at 11393.5,-1056.83 h70
  text ".Application_BuildNumber" at 12899,-1056.83 h70
  text "1" at 739.84,-1263.5 h70
  text "2" at 3235.5,-1263.5 h70
  text "3" at 5724.84,-1263.5 h70
  text "4" at 8231.51,-1263.5 h70
  text "5" at 10730.5,-1263.5 h70
  text "6" at 13235.5,-1263.5 h70
M10 Fab Notes:
  drawing of 203 lines, arcs and shapes, not listed
  text "DESIGN INFORMATION" at 12385,6066 h60
  text "BOARD SIZE" at 11369,5912 h60
  text "(REFER ALSO ARRAY/PANEL PROFILING INFORMATION)" at 12057,5910 h60
  text "X" at 12394.46,5811.68 h60
  text "2450.00MIL" at 12558,5809 h60
  text "2800.00 MIL" at 11798,5804 h60
  text "15" at 12727,5702 h60
  text "MIL" at 12917.46,5702 h60
  text "MIN. TRACK WIDTH:" at 11736,5677 h60
  text "MIL" at 12919,5576 h60
  text "7.874" at 12614,5571 h60
  text "MIN. CLEARANCE:" at 11739,5557 h60
  text "26" at 12737.71,5450 h60
  text "MIL" at 12922.46,5450 h60
  text "MIN. VIA PAD SIZE:" at 11741,5428 h60
  text "MINIMUM ANNULAR RING" at 11407.23,5320 h60
  text "0.1778mm (7MIL)" at 12401.46,5320.29 h60
  text "EXTERNAL" at 13139.46,5320 h60
  text "PER" at 11607.23,5202 h60
  text "IPC-D-275 CLASS 2 LEVEL C" at 11827.23,5202 h60
  text "MIL, HOLES" at 13315.46,5089.71 h60
  text "+/-" at 12923,5089 h60
  text "+/-" at 13777,5089 h60
  text "REGISTRATION TOLERANCES:" at 11407.23,5084 h60
  text "METAL" at 12607,5084 h60
  text "5" at 13183.2,5084 h60
  text "3" at 14016.2,5084 h60
  text "MIL" at 14132.46,5084 h60
  text "MATERIAL:" at 11332.46,4874.54 h60
  text "FR-4 High Tg" at 12318.9,4734.21 h60
  text "FR-4" at 13695.46,4727.64 h60
  text "FR-408" at 11753.46,4725.64 h60
  text "X" at 13056.4,4725.64 h60
  text "OTHER" at 13241.46,4725.64 h60
  text "63 MIL (1.6mm) +/-10%" at 12073.56,4562.92 h60
  text "THICKNESS:" at 11407.23,4558.64 h60
  text "X" at 11945.4,4558.64 h60
  text "OTHER" at 13358.46,4558.64 h60
  text "TOLERANCE:" at 11407.23,4400.64 h60
  text "X" at 12246.53,4400.64 h60
  text "ANSI IPC-6012 TYPE 3 CLASS 2" at 12433.48,4400.64 h60
  text "OTHER +/-" at 12433.46,4244.64 h60
  text "BOW & TWIST:" at 11407.23,4087.64 h60
  text "X" at 12246.53,4087.64 h60
  text "ANSI IPC-6012 TYPE 3 CLASS 2" at 12433.48,4087.64 h60
  text "OTHER +/-" at 12433.46,3929.13 h60
  text "DRILLING:" at 11332.46,3790.64 h60
  text "REFERENCE:" at 11407.23,3673.64 h60
  text "X" at 12055.46,3673.64 h60
  text "AS SHOWN" at 12242.46,3673.64 h60
  text "X" at 12956.46,3673.64 h60
  text "NC_DRILL FILES" at 13093.46,3673.64 h60
  text "PTH MIN COPPER THICKNESS:" at 11407.23,3515.64 h60
  text "X" at 12757.46,3515.64 h60
  text "1MIL" at 12894.46,3515.64 h60
  text "OTHER" at 13391.46,3515.64 h60
  text "BOARD FINISH:" at 11332.46,3356.64 h60
  text "SILKSCREEN:" at 11487.68,3238.64 h60
  text "X" at 12436.46,3238.64 h60
  text "TOP" at 12562.46,3238.64 h60
  text "X" at 12946.46,3238.64 h60
  text "BOTTOM" at 13073.46,3238.64 h60
  text "SILKSCREEN COLOR:" at 11487.68,3071.64 h60
  text "X" at 12435.42,3071.64 h60
  text "WHITE" at 12562.46,3071.64 h60
  text "OTHER" at 13073.46,3071.64 h60
  text "SOLDER RESIST COLOR:" at 11487.68,2901.64 h60
  text "X" at 12055.42,2742.44 h60
  text "GREEN" at 12182.46,2742.44 h60
  text "BLUE" at 12773.46,2742.44 h60
  text "OTHER" at 13311.46,2742.44 h60
  text "IMMERSION GOLD (ENIG)" at 12393.46,2553.92 h60
  text "ENEPIG" at 13731,2550.64 h60
  text "SURFACE FINISH:" at 11332.46,2549.64 h60
  text "X" at 12206.51,2549.64 h60
  text "IMM. TIN/SILVER OR EQUIV" at 11662,2392.64 h60
  text "OTHER" at 13093.46,2392.64 h60
  text "ARRAY/PANEL:" at 11332.46,2213.64 h60
  text "CUT AND TRIM PER MECH LAYER 1" at 12393.46,2209.35 h60
  text "N.C. ROUTE" at 12393.46,2057.64 h60
  text "X" at 13072.46,2057.64 h60
  text "V. SCORE" at 13259.46,2057.64 h60
  text "CERTIFICATION:" at 11332.46,1920.64 h60
  text "MATERIALS AND WORKMANSHIP FOR ALL PCBS" at 12057.46,1920.64 h60
  text "TO MEET OR EXCEED THE REQUIREMENTS OF:" at 12057.46,1822.64 h60
  text "X" at 11683.96,1686.13 h60
  text "ANSI IPC-A-600F CLASS ->" at 11822.96,1686.13 h60
  text "X" at 13462.02,1686.13 h60
  text "2" at 13580.96,1686.14 h60
  text "1" at 13265.96,1684.64 h60
  text "3" at 13934.96,1684.64 h60
  text "X" at 11686.02,1526.64 h60
  text "UL 94V-0" at 11822.96,1526.64 h60
  text "X" at 12498.02,1526.64 h60
  text "RoHS" at 12634.96,1526.64 h60
  text "OTHER" at 13279.36,1526.64 h60
  text "PER ORDER" at 13676.42,1526.64 h60
  text "X" at 13473,1395 h60
  text "VIA TENTING:" at 12531,1387 h60
  text "ADDITIONAL REQUIREMENTS:" at 11332.46,1385.64 h60
  text "YES" at 13228,1386 h60
  text "NO" at 13644,1381 h60
  text "MICROSECTION:" at 11407.23,1270.64 h60
  text "YES" at 12312.96,1270.64 h60
  text "IMPEDANCE CONTROL:" at 12503,1266 h60
  text "NO" at 13798,1266 h60
  text "YES" at 13423,1260 h60
  text "X" at 13981,1257.16 h60
  text "REQUIRED" at 13174.46,1114.49 h60
  text "BARE BOARD ELEC. TEST:" at 11407.23,1111.64 h60
  text "NONE" at 12712.96,1111.64 h60
  text "X" at 13047.46,1111.64 h60
  text "PER ORDER" at 13766.46,1111.64 h60
  text "MANUFACTURER'S UL:" at 11407.23,954.64 h60
  text "RAIL" at 12572.96,950.35 h60
  text "METAL" at 13064.77,950.35 h60
  text "X" at 13440,950 h60
  text "SILK" at 13576.46,950.35 h60
M11 Gerber Information:
  lines w10: -292,-930.17 6308,-930.17 ; -292,-726.83 6310,-726.83 ; -292,-523.5 -292,-1133.5 3713,-1133.5 6310,-1133.5 6310,-523.5 -291.5,-523.5 -291.5,-1133.5 1284,-1133.5 ; 2173,-1133.5 2173,-523.5 ; 3440,-726.83 3440,-523.5 ; 4280,-726.83 4280,-523.5 ; 4902,-1140 4902,-937.17
  text "ALL ARTWORK VIEWED FROM TOP SIDE" at -228.5,-655.67 h60
  text "BOARD #:" at 2248,-655.67 h60
  text ".PRJ_Number" at 2793.5,-655.67 h60
  text "REV:" at 3638,-655.67 h60
  text ".PCB_Rev" at 3929.5,-655.67 h60
  text "SVN REV:" at 4476,-655.67 h60
  text ".VersionControl_RevNumber" at 4982,-655.67 h60
  text "LAYER NAME =" at -228.5,-858.49 h60
  text "PLOT NAME =" at -228.5,-1064.34 h60
  text ".plot_File_Name" at 577,-1064.34 h60
  text "GENERATED    :" at 2250,-1064.34 h60
  text ".Print_Date" at 3119.5,-1064.34 h60
  text ".Print_Time" at 3848.5,-1064.34 h60
  text "TEXAS INSTRUMENTS" at 5113,-1064.34 h60
M12 Stackup:
  lines w8: 11271,7382.5 14163,7382.5 ; 11271,7534 14163,7534 ; 11211,6424 ccw(c11260,6424) 11260,6375 14174,6375 ccw(c14174,6424) 14223,6424 14223,7664 ccw(c14174,7664) 14174,7713 11260,7713 ccw(c11260,7664) 11211,7664 11211,6424
  text "Layer Stack Up Detail for: TIDA-00442-E2.PcbDoc" at 11271,7584.3 h54
  text "Layer" at 11271,7477.5 h35
  text "Gerber" at 12299.73,7477.5 h35
  text "Copper" at 12855.75,7477.5 h35
  text "Dielectric" at 13468.91,7477.5 h35
  text "Name" at 11271,7407.5 h35
  text "Document" at 12299.73,7407.5 h35
  text "Thickness" at 12855.75,7407.5 h35
  text "Material" at 13468.91,7407.5 h35
  text "Top Solder Mask" at 11271,7308.81 h49
  text "(.GTS)" at 12299.73,7308.81 h49
  text "Solder Resist" at 13468.91,7308.81 h49
  text "Top Layer" at 11271,7169.44 h49
  text "(.GTL)" at 12299.73,7169.44 h49
  text "1.4mil" at 12855.75,7169.44 h49
  text "FR-4" at 13468.91,7099.75 h49
  text "GND" at 11271,7030.06 h49
  text "(.G1)" at 12299.73,7030.06 h49
  text "1.4mil" at 12855.75,7030.06 h49
  text "FR-4" at 13468.91,6960.38 h49
  text "POWER" at 11271,6890.69 h49
  text "(.G2)" at 12299.73,6890.69 h49
  text "1.4mil" at 12855.75,6890.69 h49
  text "FR-4" at 13468.91,6821 h49
  text "Bottom Layer" at 11271,6751.31 h49
  text "(.GBL)" at 12299.73,6751.31 h49
  text "1.4mil" at 12855.75,6751.31 h49
  text "Bottom Solder Mask" at 11271,6611.94 h49
  text "(.GBS)" at 12299.73,6611.94 h49
  text "Solder Resist" at 13468.91,6611.94 h49
M13 Component Bodies Top:
  text ".Layer_Name" at 577,-858.49 h60
M14 Component Bodies Bottom:
  text ".Layer_Name" at 577,-858.49 h60
M15 Courtyards Top:
  text ".Layer_Name" at 577,-858.49 h60
M16 Courtyards Bottom:
  text ".Layer_Name" at 577,-858.49 h60
Drill Drawing:
  text "Drill Table" at 3899,1700 h60
  text ".legend" at 3904,366 h60
  text "DRILL TOLERANCE" at 3907,178 h60
  text "FOR PTH +/- 3MIL" at 3907,78 h60
  text "12mil drill:+0/-12mil" at 3903,-15 h60
  text "20mil drill:+0/-20mil" at 3901,-114 h60
  text ".Layer_Name" at 577,-858.49 h60

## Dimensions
0,0 to 2800,0 on M2 Board Dimensions
0,0 to 0,2450 on M2 Board Dimensions
0,-400 to 1000,-400 on M2 Board Dimensions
